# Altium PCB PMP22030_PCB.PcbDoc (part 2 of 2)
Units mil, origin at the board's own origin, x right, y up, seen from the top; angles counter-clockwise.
Board outline 4950 x 3450 mil, 4 copper layers (Top Layer, Signal Layer 1, Signal Layer 2, Bottom Layer), stack 55.6 mil thick; 125 components, 59 nets, 280 pads, 156 vias.
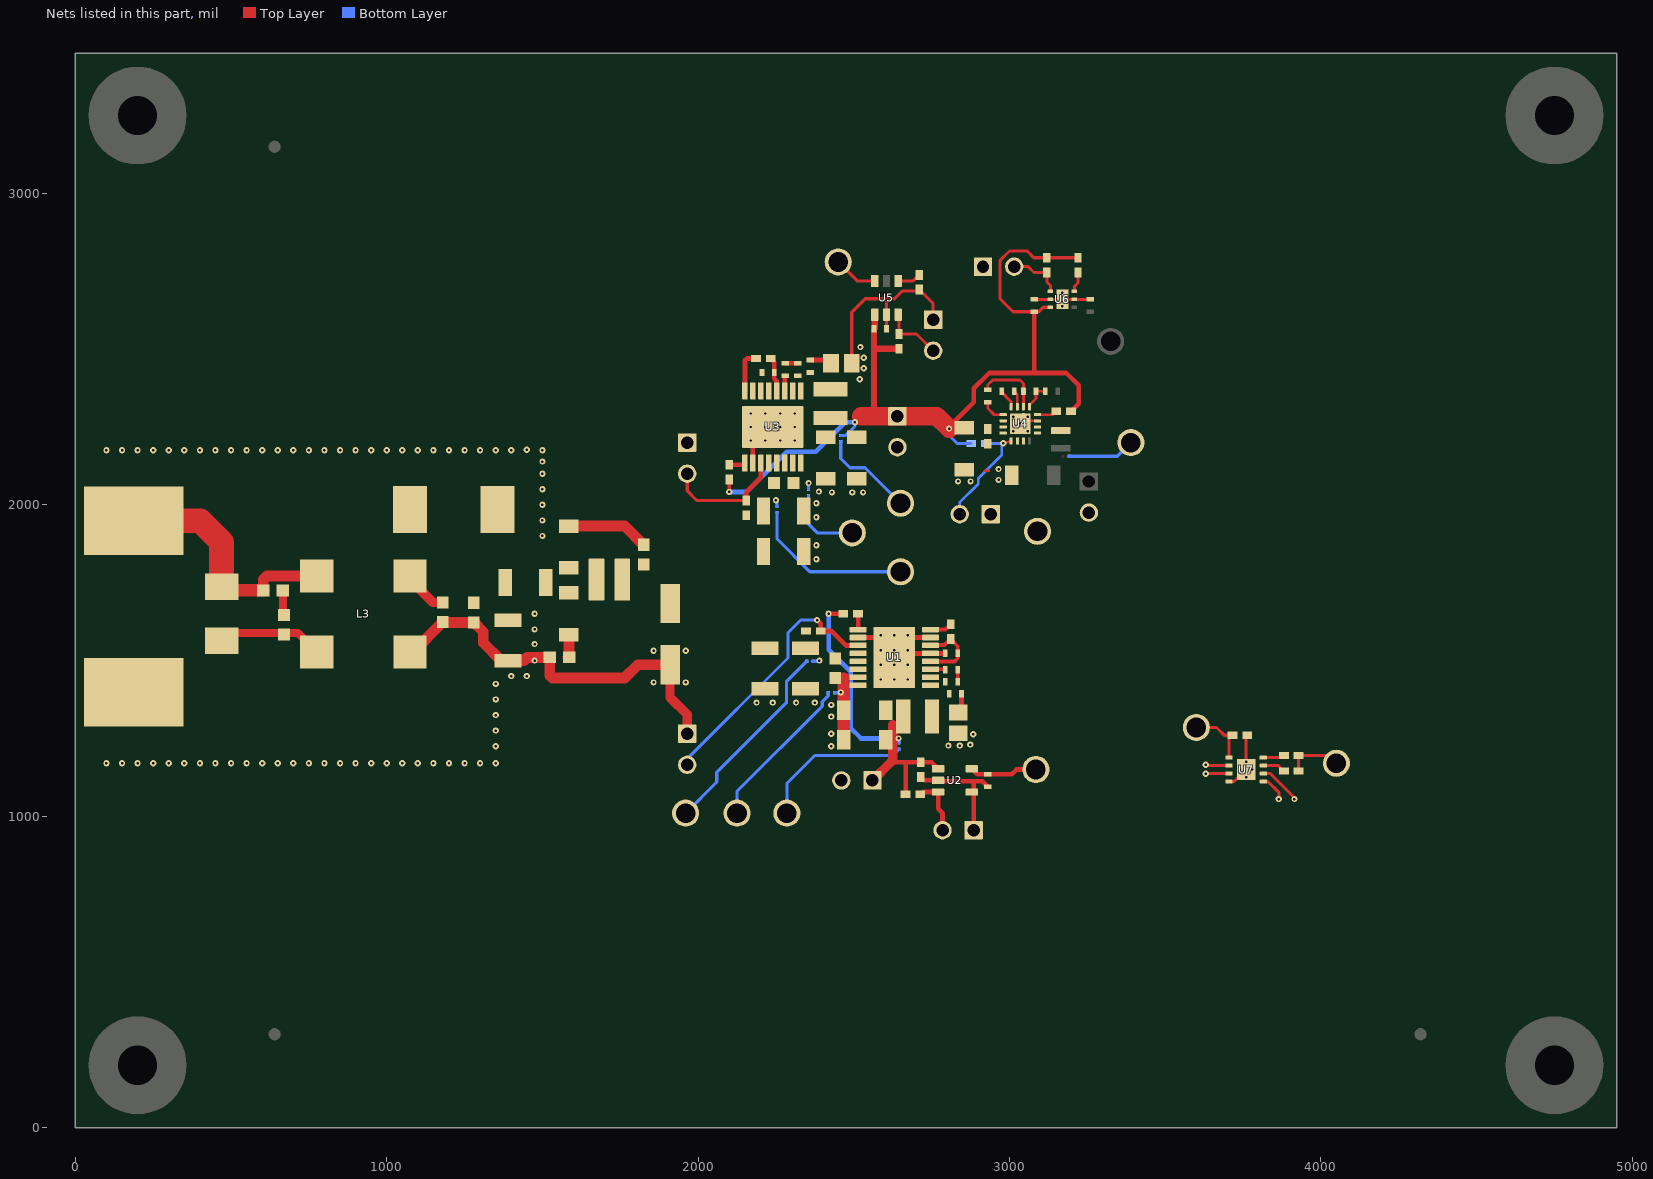
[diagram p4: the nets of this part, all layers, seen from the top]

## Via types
v1: diameter 20, hole 8, Top Layer to Bottom Layer, tented both sides, 121 vias
v2: diameter 19.68, hole 7.87, Top Layer to Bottom Layer, 23 vias
v3: diameter 19.68, hole 7.87, Top Layer to Bottom Layer, tented both sides, 12 vias

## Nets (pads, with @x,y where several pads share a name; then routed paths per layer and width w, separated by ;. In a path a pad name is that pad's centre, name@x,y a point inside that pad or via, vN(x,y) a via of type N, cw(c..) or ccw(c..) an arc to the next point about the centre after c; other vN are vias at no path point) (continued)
3V3: C25.1 C26.1 C27.1 C28.1 C33.1 C35.1 J7.1 L5.2 NT5.1 R12.1 R13.1 R16.2 R17.1 R18.1 R19.2 U4.10 U4.11 U4.12 U5.1 U6.6 | length 2907.1
  Top Layer w10: v1(2100,2041.46) R12.1@2100,2081.38 ; C33.1@2564.68,2564 C33.1@2567.6,2566.91 ; v1(2806.18,2245) 2853.07,2245 C27.1@2855,2246.93 ; U6.6@3131.61,2634.41 3108.91,2634.41 3094.5,2620 C35.1@3080,2620 3011.1,2620 2970,2661.1 2970,2785 3000,2815 3057,2815 3078.38,2793.62 R18.1@3120,2793.62 R19.2@3220,2793.62
  Top Layer w15: v1(2503.67,2265) 2523.67,2285 ; v1(2806.18,2245) 2806.18,2250.71 2885,2329.53 2885,2373.72 2934.73,2423.45 3080,2423.45 ; C35.1@3080,2620 3080,2423.45 ; R16.2@3197.68,2301 3222.06,2325.38 3222.06,2383.72 3182.34,2423.45 3080,2423.45
  Top Layer w20: C33.1@2564.68,2564 2564.68,2501.38 ; 2566.5,2285 2564.68,2286.81 2564.68,2501.38 ; C33.1@2567.6,2566.91 U5.1@2567.6,2610.87 ; J7.1@2640,2285 J7.1@2645,2290 ; R17.1@2645,2501.38 2564.68,2501.38
  Top Layer w60: 2523.67,2285 2566.5,2285 J7.1@2640,2285 2766.18,2285 v1(2806.18,2245)
  Bottom Layer w10: NT5.1@2458,2223 2474,2223 2503.67,2252.67 v1(2503.67,2265) ; v1(2806.18,2245) 2806.18,2222.82 2832,2197 R13.1@2877.06,2197
  Bottom Layer w15: v1(2100,2041.46) 2156.46,2041.46 2285,2170 2378.23,2170 2473.23,2265 v1(2503.67,2265)
3V3SW: 3V3SW.1 U5.6 | length 142.8
  Top Layer w10: 3V3SW.1@2450,2780 2510.87,2719.13 U5.6@2567.6,2719.13
5V: C15.1 C16.1 C17.1 J3.1 L4.2 NT2.1 R5.1 R6.1 U2.1 | length 1098.3
  Top Layer w15: v1(2419.21,1650) R5.1@2466.38,1650 ; 2625,1180 2618.62,1173.62 2670,1173.62 ; R6.1@2666.38,1070 2666.38,1170 2670,1173.62 ; U2.1@2770.87,1152.4 2749.65,1173.62 C17.1@2715,1173.62 2670,1173.62
  Top Layer w30: J3.1@2560,1115 2618.62,1173.62 ; 2625,1180 2625,1293.7
  Bottom Layer w10: NT2.1@2645,1235 v1@2645,1248.75
  Bottom Layer w15: v1(2419.21,1650) 2419.21,1534.26 2490,1463.47 2490,1282.9 2523.14,1249.76 v1(2643.99,1249.76) v1@2645,1248.75
AGND: C32.2 NT8.2 R15.1 U4.6 | length 216.3
  Top Layer w9: C32.2@2930,2370 2930,2385 2946.22,2401.22 3033.78,2401.22 3045,2390 R15.1@3045,2365 3044.84,2364.84 U4.6@3044.84,2315.12
CBOOT: R9.2 U3.3 | length 49.5
  Top Layer w15: U3.3@2278.39,2366.14 2278.39,2413.39 R9.2@2280,2415
CBOOT1: R3.2 U1.3 | length 48.2
  Top Layer w12: U1.3@2746.14,1471.61 2792.92,1471.61 R3.2@2793.89,1470.64
CGND: C7.1 D2.1 J2.1 L3.2 | length 341
  Top Layer w25: D2.1@470,1562.99 495.51,1588.5 670,1588.5 714.84,1588.5 L3.2@775.39,1527.95
CN: C31.2 U4.8 | length 62.5
  Top Layer w9: C31.2@2975,2365 2975,2361.61 3005.47,2331.14 U4.8@3005.47,2315.12
CP: C31.1 U4.7 | length 54.1
  Top Layer w9: C31.1@3015,2365 3025.13,2354.87 U4.7@3025.13,2315.15
CT: C36.2 U5.4 | length 75.7
  Top Layer w10: U5.4@2642.4,2719.13 2690.51,2719.13 C36.2@2710,2738.62
CWD: U7.2 | length 74.9
  Top Layer w10: v1@3630,1162.8 U7.2@3704.88,1162.8
  other v1: 3630,1165
EN: J8.2 R10.2 U3.11 | length 397.5
  Top Layer w10: J8.2@1965,2100 1965,2045 1996.38,2013.62 R10.2@2155,2013.62
  Top Layer w15: R10.2@2155,2013.62 2155,2040 2201.61,2086.61 U3.11@2201.61,2133.86
EN1: J4.2 R4.2 U1.11 | length 847.5
  Top Layer w15: v1(2382.07,1630) 2393.62,1618.44 R4.2@2393.62,1595 2427.99,1595 2474.61,1548.39 U1.11@2513.86,1548.39
  Bottom Layer w10: J4.2@1965,1165 1965,1184.18 2288.94,1508.12 2288.94,1588.88 2330.07,1630 v1(2382.07,1630)
EN1V1: J9.2 R13.2 U4.13 | length 367.1
  Top Layer w9: v1(2980,2197.99) U4.13@3005.47,2204.88
  Bottom Layer w9: J9.2@2840,1970 2840,2007.4 2899.6,2067 2899.6,2084.6 2975,2160 2975,2192.99 v1@2979.01,2197 ; R13.2@2924.31,2197 v1@2979.01,2197 ; v1(2980,2197.99) v1@2979.01,2197
EN1V8: J11.2 R18.2 U6.4 | length 178.3
  Top Layer w10: J11.2@3015,2765 3060,2765 3078.62,2746.38 R18.2@3120,2746.38 3120,2715.91 3131.61,2704.29 U6.4@3131.61,2685.59
ENL: J5.2 R6.2 U2.3 | length 188.8
  Top Layer w15: R6.2@2713.62,1070 2721.22,1077.6 U2.3@2770.87,1077.6 2770.87,1024.13 2785,1010 J5.2@2785,955
ENP: J10.2 R17.2 U5.3 | length 195.5
  Top Layer w10: U5.3@2642.4,2610.87 2645,2608.27 R17.2@2645,2548.62 2701.38,2548.62 J10.2@2755,2495
FB: R12.2 U3.9 | length 52.6
  Top Layer w15: R12.2@2100,2128.62 2145.2,2128.62 U3.9@2150.43,2133.86
FB1V1: R11.1 R15.2 U4.5 | length 88.4
  Top Layer w9: U4.5@3064.53,2315.12 3064.53,2320.66 3085,2341.13 R15.2@3085,2365 R11.1@3115,2365
FB_U1: R5.2 U1.9 | length 50.2
  Top Layer w15: U1.9@2513.86,1599.57 R5.2@2513.86,1649.76
GND: C2.2 C3.2 C5.2 C6.1 C8.2 C9.2 C12.2 C13.2 C14.2 C15.2 C16.2 C17.2 C18.2 C19.2 C22.2 C23.2 C24.2 C25.2 C26.2 C27.2 C28.2 C29.2 C30.2 C33.2 C34.2 C35.2 C36.1 C37.2 GND.1 J3.2 J4.1 J5.1 J6.2 J7.2 J8.1 J9.1 J10.1 J11.1 L3.3 NT3.2 NT7.2 NT8.1 R1.1 R2.1 R8.1 U1.5 U1.7 U1.10 U1.14 U1.15 U1.16 U1.17@2630,1510 U2.2 U2.4 U3.5 U3.6 U3.7 U3.10 U3.14 U3.15 U3.16 U3.17@2240,2250 U4.3 U4.14 U4.15 U4.17@3035,2260 U5.2 U6.2 U6.5 U6.7@3170,2660 U7.4 U7.9 | length 3800.3
  Top Layer w9: 2920.64,2109.53 2933.23,2109.53 ; v2(3035,2260) 3044.84,2269.84 U4.3@3090.12,2269.84
  Top Layer w10: R8.1@2493.46,2455 2493.46,2618.46 2536.69,2661.69 2605,2661.69 ; C33.2@2604.68,2564 2604.68,2610.55 U5.2@2605,2610.87 ; U5.2@2608.31,2614.17 U5.2@2605,2610.87 ; J10.1@2755,2595 2755,2646.38 C36.1@2710,2691.38 2705.2,2686.57 2655.47,2686.57 2630.59,2661.69 2605,2661.69 ; C35.2@3080,2660 U6.5@3131.61,2660 U6.7@3170,2660 U6.2@3208.39,2660 C34.2@3255,2660 ; U7.4@3704.88,1111.61 3721.61,1111.61 U7.9@3760,1150 3760,1256.38 C37.2@3763.62,1260 ; U5.2@2605,2610.87 2605,2661.69
  Top Layer w15: U3.10@2176.02,2133.86 2176.02,2186.02 U3.17@2240,2250 ; U1.10@2513.86,1573.98 2566.02,1573.98 U1.17@2630,1510 U1.17@2642.8,1522.8 ; C17.2@2715,1126.38 2726.38,1115 U2.2@2770.87,1115 2770.87,1112.13 2885,1112.13 ; U1.7@2746.14,1573.98 2693.98,1573.98 U1.17@2642.8,1522.8 ; C19.2@2793.99,1523.64 2793.15,1522.8 U1.5@2746.14,1522.8 U1.17@2642.8,1522.8 ; J5.1@2885,955 2885,1112.13 ; C18.2@2930,1095 2912.87,1112.13 2885,1112.13
  Top Layer w30: C2.2@1910,1486.57 1910,1381.56 1965,1326.56 J4.1@1965,1265
  Top Layer w35: L3.3@1074.61,1527.95 1084.45,1527.95 C6.1@1180,1623.5 1181,1622.5 C9.2@1280,1622.5 1310,1592.5 1310,1556.99 1366.95,1500.04 C8.2@1390,1500.04 1440.91,1500.04 1450.87,1510 R1.1@1523.5,1510 1523.5,1452.52 1532.52,1443.5 1763.65,1443.5 1806.72,1486.57 C2.2@1910,1486.57 ; C3.2@1585,1931.93 1764.57,1931.93 C5.2@1825,1871.5
  Top Layer w40: 2467.27,1441 2468.07,1440.2 C16.2@2468.07,1340 C15.2@2468.07,1245
  Bottom Layer w6: v1@2457,1396.64 v1(2458,1397.64)
  Bottom Layer w10: NT7.2@2355,2049.21 v1(2355,2070) ; NT3.2@2437.99,1396.64 v1@2457,1396.64
  other v1: 100,1170 150,1170 200,1170 250,1170 300,1170 350,1170 400,1170 450,1170 500,1170 550,1170 600,1170 650,1170 700,1170 750,1170 800,1170 850,1170 900,1170 950,1170 1000,1170 1050,1170 1100,1170 1150,1170 1200,1170 1250,1170 1300,1170 1350,1170 1350,1225 2427.99,1225 2804.03,1226.99 2840,1226.99 2874.37,1230.12 2884.03,1263.51 2427.99,1265 1350,1275 2427.99,1320 1350,1325 2427.99,1357.5 2187.67,1365 2240,1365 2314.8,1365 2375,1365 1350,1375 1350,1425 1856.97,1429.64 1960,1429.64 1400,1450 1450,1450 1475,1500 1856.97,1531.54 1960,1531.54 1475,1552.72 1475,1600 1475,1650 2380,1825 2380,1870 1500,1900 1500,1950 2380,1960 1500,2000 2380,2005 2430,2040 2495,2040 2530,2040 2388.1,2042.8 1500,2050 2835,2075 2875,2075 2965,2080 1500,2100 2965,2115 1500,2138.89 100,2175 150,2175 200,2175 250,2175 300,2175 350,2175 400,2175 450,2175 500,2175 550,2175 600,2175 650,2175 700,2175 750,2175 800,2175 850,2175 900,2175 950,2175 1000,2175 1050,2175 1100,2175 1150,2175 1200,2175 1250,2175 1300,2175 1350,2175 1400,2175 1500,2175 1450,2176.66 2519.46,2403.23 2532.3,2438.83 2532.3,2472.56 2521.32,2506.81
  other v2: 3760,1125.39 3740.31,1150 3779.69,1150 3760,1174.61 2586.69,1486.38 2630,1486.38 2673.31,1486.38 2586.69,1533.62 2630,1533.62 2673.31,1533.62 2216.38,2206.69 2263.62,2206.69 3011.77,2236.77 3058.23,2236.77 2216.38,2250 2263.62,2250 3011.77,2283.23 3058.23,2283.23 2216.38,2293.31 2263.62,2293.31 3170,2638.35 3170,2681.65
  other v3: 2586.69,1439.13 2630,1439.13 2673.31,1439.13 2586.69,1580.87 2630,1580.87 2673.31,1580.87 2169.13,2206.69 2310.87,2206.69 2169.13,2250 2310.87,2250 2169.13,2293.31 2310.87,2293.31
MR: U7.3 | length 75.1
  Top Layer w10: v1(3630,1136.65) 3630.55,1137.2 U7.3@3704.88,1137.2
Net1V1_1: 1V1.1 NT6.2 | length 216.5
  Bottom Layer w10: NT6.2@3191.68,2156 3346,2156 1V1.1@3390,2200
Net3V3_1: 3V3.1 NT5.2 | length 312
  Bottom Layer w10: 2458,2155 2458,2148.77 ; NT5.2@2458,2203 2458,2148.77 ; 3V3.1@2650,2005 2535.95,2119.05 2487.72,2119.05 2458,2148.77
Net3V3LDO_1: 3V3LDO.1 C18.1 U2.5 | length 219.3
  Top Layer w15: U2.5@2879.13,1152.4 2896.54,1135 C18.1@2930,1135 3007.76,1135 3022.76,1150 3V3LDO.1@3085,1150
Net5V_1: 5V.1 NT2.2 | length 500.6
  Bottom Layer w10: 5V.1@2285,1010 2285,1105 2375,1195 2625,1195 NT2.2@2645,1215
NetC1_1: C1.1 D2.2 J1.1 L3.1 | length 805.2
  Top Layer w25: D2.2@470,1737.01 D2.2@482.01,1725
  Top Layer w35: C1.1@603.5,1725 603.5,1760.55 615,1772.05 L3.1@775.39,1772.05
  Top Layer w40: D2.2@482.01,1725 C1.1@603.5,1725
  Top Layer w80: J1.1@187.01,1948.82 401.18,1948.82 470,1880 D2.2@470,1737.01
NetC1_2: C1.2 C7.2 | length 75
  Top Layer w25: C1.2@666.5,1725 666.5,1655 C7.2@670,1651.5
NetC4_2: C4.2 R1.2 | length 74.5
  Top Layer w35: R1.2@1581.5,1510 1585,1513.5 C4.2@1585,1583.07
NetC8_1: C8.1 C9.1 D1.1 L1.1
NetC10_1: C10.1 R2.2 | length 63.8
  Top Layer w15: R2.2@2835,1333.46 2846.18,1344.65 C10.1@2846.18,1392.64
NetC11_1: C11.1 R3.1 | length 39
  Top Layer w12: R3.1@2833.89,1470.64 2833.89,1431.74 C11.1@2833.99,1431.64
NetC20_1: C20.1 R8.2 | length 70.7
  Top Layer w15: C20.1@2360,2465 2416.54,2465 R8.2@2426.54,2455
NetC21_1: C21.1 R9.1 | length 40
  Top Layer w15: R9.1@2280,2455 C21.1@2320,2455
NetGNDS1_1: GNDS1.1 NT3.1 | length 508
  Bottom Layer w10: GNDS1.1@2125,1010 2125,1080 2398.7,1353.7 2398.7,1368.07 2417.99,1387.36 NT3.1@2417.99,1396.64
NetGNDS_1: GNDS.1 NT7.1 | length 243.1
  Bottom Layer w10: NT7.1@2355,2029.21 2355,1960 2355,1937.47 2382.47,1910 2405,1910 GNDS.1@2495,1910
NetNT1_2: NT1.2 VIN2.1 | length 648.8
  Bottom Layer w10: VIN2.1@1960,1010 2060,1110 2060,1140.87 2283.38,1364.25 2283.38,1431.93 NT1.2@2349.09,1497.64
NetNT4_2: NT4.2 VIN1.1 | length 524.8
  Bottom Layer w10: NT4.2@2253.35,1975 2253.35,1890.63 2358.98,1785 VIN1.1@2650,1785
NetR20_2: R20.2 R21.2 TP13.1 | length 181.7
  Top Layer w10: R21.2@3928.62,1145 R20.2@3928.62,1195 4025,1195 TP13.1@4050,1170
PG1V1: R16.1 U4.4 | length 65.1
  Top Layer w9: U4.4@3090.12,2289.53 3138.97,2289.53 R16.1@3150.44,2301
PG1V8: R19.1 U6.3 | length 65.6
  Top Layer w10: U6.3@3208.39,2685.59 3208.39,2700.81 3220,2712.43 R19.1@3220,2746.38
PGOOD: R14.2 U3.8 | length 136.3
  Top Layer w15: U3.8@2150.43,2366.14 2150.43,2463.98 2156.46,2470 R14.2@2186.38,2470
PGOOD1: R7.2 U1.8 | length 71.8
  Top Layer w12: U1.8@2746.14,1599.57 2794.3,1599.57 R7.2@2810.99,1616.26
RSET: R20.1 U7.8 | length 69
  Top Layer w10: U7.8@3815.12,1188.39 3874.76,1188.39 R20.1@3881.38,1195
SET1: U7.5 | length 86
  Top Layer w10: U7.5@3815.12,1111.61 3829.95,1111.61 3865,1076.56 v1(3865,1055)
SS1V1: C32.1 U4.9 | length 78.1
  Top Layer w9: C32.1@2930,2330 2930,2310.5 2950.97,2289.53 U4.9@2979.88,2289.53
SW: C20.2 C21.2 L5.1 U3.1 U3.2
SW1: C10.2 C11.2 L4.1 U1.1 U1.2
SW1V1: L6.1 U4.1 U4.2
VBATT: C6.2 D1.2 L3.4 | length 147.7
  Top Layer w30: L3.4@1074.61,1772.05 1074.61,1760.39 1148.5,1686.5 C6.2@1180,1686.5
VCC: C30.1 R14.1 U3.4 | length 111.8
  Top Layer w15: R14.1@2233.62,2470 2245,2458.62 C30.1@2245,2425 2245,2405.36 2252.8,2397.57 U3.4@2252.8,2366.14
VCC1: C19.1 R7.1 U1.4 U1.6 | length 237.2
  Top Layer w12: U1.4@2746.14,1497.2 2823.7,1497.2 2833.99,1507.5 C19.1@2833.99,1523.64 2833.99,1546.02 R7.1@2810.99,1569.02 2791.49,1549.51 2746.14,1549.51 U1.6@2746.14,1548.39
VDD: C37.1 TP12.1 U7.1 | length 203.1
  Top Layer w10: TP12.1@3600,1285 3665,1285 3690,1260 C37.1@3716.38,1260 3704.88,1248.5 U7.1@3704.88,1188.39
VFILT: C3.1 C4.1 L1.2 L2.1
VIN: C2.1 C5.1 C12.1 C13.1 C14.1 C22.1 C23.1 C24.1 L2.2 NT1.1 NT4.1 R4.1 R10.1 U1.12 U1.13 U3.12 U3.13 | length 42.8
  Bottom Layer w10: v1(2250,2015) 2253.35,2011.65 NT4.1@2253.35,1995 ; NT1.1@2369.09,1497.64 2387.2,1497.64 v1(2389.57,1500)
WDI: U7.6 | length 136.9
  Top Layer w10: U7.6@3815.12,1137.2 3837.8,1137.2 3915,1060 v1(3915,1055)
WDO: R21.1 U7.7 | length 73.6
  Top Layer w10: U7.7@3815.12,1162.8 3863.58,1162.8 R21.1@3881.38,1145
pads on no net: FID1.1 FID2.1 FID3.1 H1.1 H2.1 H3.1 H4.1 H5.0 H6.0 H7.0 H8.0 LBL1.0 U1.17@2630,1510 U3.17@2240,2250 U4.17@3035,2260 U5.5 U6.7@3170,2642.28 U6.7@3170,2677.72

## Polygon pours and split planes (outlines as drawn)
GND on Signal Layer 1 "SIGNAL_LAYER_1_GND_P004" (solid, remove dead copper, pour order 4): 0,0 0,3450 4950,3450 4950,0
GND on Top Layer "TOP_LAYER_GND_P000" (solid, remove dead copper, pour order 0): 0,0 0,3450 4950,3450 4950,0
GND on Signal Layer 2 "SIGNAL_LAYER_2_GND_P006" (solid, remove dead copper, pour order 6): 0,0 0,3450 4950,3450 4950,0
GND on Bottom Layer "BOTTOM_LAYER_GND_P008" (solid, remove dead copper, pour order 8): 0,0 0,3450 4950,3450 4950,0

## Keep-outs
Keep-Out Layer:
  text ".Layer_Name" at 577,-858.49 h60

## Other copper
Top Layer:
  region net VIN: 1866.73,1616.26 2043.86,1616.26 2043.86,1492.64 2259.21,1492.64 2259.21,1982.13 1866.73,1982.13
  pour cut-out: 0,1195 1295,1195 1295,2150 5,2150
  region net GND: 3000,2144.57 2804.61,2144.57 2804.61,2050 3000,2050
  region net GND: 3020,2237.5 3020,2175.35 2985,2140.35 2985,2050 3050,2050 3050,2237.5
  region net 1V1: 3115,2198.7 3115,2061.3 3205,2061.3 3205,2198.7
  region net SW1V1: 3080,2255 3200.43,2255 3200.43,2220 3080,2220
  region net 3V3: 2990,2269.83 2823.7,2270 2823.7,2225 2990,2225
  region net GND: 2170,2310 2233.62,2310 2233.62,2391.93 2225,2400.55 2225,2440 2170,2440
  region net 3V3: 2367.5,2305 2367.5,2195 2549.37,2195 2549.37,2305
  region net SW: 2300,2341.13 2300,2401.22 2306.22,2407.44 2306.22,2430 2375,2430 2388.1,2416.9 2464.95,2416.9 2481.85,2400 2481.85,2340
  region net VIN: 2260,2161.5 2260,1798.07 2135,1798.07 2135,1982.13 2172.17,1982.13 2222.87,2032.84 2222.87,2161.5
  region net GND: 2274.06,2163.39 2274.06,2049.21 2315,2049.21 2315,1805.12 2420,1805.12 2420,2009.97 2555,2010.07 2555,2163.39
  region net VIN: 2170,1518.46 2170,1608.43 2365,1608.43 2365,1518.46
  region net GND: 2169.13,1471.61 2481.85,1471.61 2481.85,1480 2595,1480 2595,1390 2169.13,1390
  region net VIN: 2543.39,1530 2543.39,1490 2170,1490 2170,1530
  region net 5V: 2683.33,1377.4 2575,1377.4 2575,1210 2683.33,1210
  region net SW1: 2720,1265 2720,1450 2778.79,1450 2783.37,1445.42 2817.18,1445.42 2817.18,1378.86 2804.61,1378.86 2780,1354.25 2780,1265
  region net VIN: 1730,1829.57 1945,1829.57 1945,1615 1730,1615
  region net VFILT: 1700,1829.57 1477.89,1829.57 1477.89,1690 1700,1690
  region net NetC8_1: 1260,1665 1260,2061.01 1435,2061.01 1435,1605 1345,1605 1345,1665
  region net VBATT: 1020,2060 1021.01,2061.01 1135,2061.01 1135,1713.98 1020,1713.98
  region net CGND: 850,1605 850,1277.64 847.64,1280 35,1280 35,1605
  text ".Layer_Name" at 577,-858.49 h60
Signal Layer 1:
  pour cut-out: 0,1195 1295,1195 1295,2150 5,2150
Signal Layer 2:
  pour cut-out: 0,1195 1295,1195 1295,2150 5,2150
Bottom Layer:
  pour cut-out: 0,1195 1295,1195 1295,2150 5,2150
  region: 2120.5,2438.78
  text ".Layer_Name" at 577,-858.49 h60

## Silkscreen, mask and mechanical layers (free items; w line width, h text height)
Top Overlay:
  text "EN 1V8" at 3043.35,2835 h72.83 r90
  text "GND" at 2937,2831 h72.83 r90
  text "GND" at 2820,2565 h72.83
  text "EN 3V3SW" at 2817.6,2505 h72.83
  text "3V3" at 2615,2237.5 h72.83
  text "GND" at 1755,2182 h72.83
  text "GND" at 2750,2100 h72.83 r90
  text "EN 3V3" at 1680,2073 h72.83
  text "1V1" at 3310,2052 h72.83
  text "GND" at 3181.68,1911 h72.83
  text "EN 1V1" at 2860,1695 h72.83 r90
  text "GND" at 2995,1625 h72.83 r90
  text "GND" at 1739,1239 h72.83
  text "EN 5V" at 1706,1137 h72.83
  text "GND" at 2485,910 h72.83 r90
  text "WATCHDOG / SUPERVISOR" at 3599.86,884 h72.83
  text "5V" at 2590,880 h72.83 r90
  text "GND" at 2908.85,710 h72.83 r90
  text "EN 3V3LDO" at 2817.18,645 h72.83 r90
  text "'.PRJ_Number'.PCB_Rev" at 1845,125.77 h108.27
  text ".Layer_Name" at 577,-858.49 h60
Bottom Overlay:
  text ".Layer_Name" at 577,-858.49 h60
Top Paste:
  text ".Layer_Name" at 577,-858.49 h60
Bottom Paste:
  text ".Layer_Name" at 577,-858.49 h60
Top Solder:
  text ".Layer_Name" at 577,-858.49 h60
  text ".Layer_Name" at 577,-858.49 h60
Bottom Solder:
  text ".Layer_Name" at 577,-858.49 h60
Drill Guide:
  text ".Layer_Name" at 577,-858.49 h60
M1 Board Outline:
  the board outline again, w10
  text ".Layer_Name" at 577,-858.49 h60
M2 Board Dimensions:
  rectangle: 0,-275 125,-150
  rectangle: 125,-400 500,-275
  lines w7: 0,-275 1000,-275 ; 125,-400 125,-150 ; 250,-400 250,-150 ; 500,-400 500,-150 ; 750,-400 750,-150 ; 0,-400 1000,-400 1000,-150 0,-150 0,-400
  text ".Layer_Name" at 577,-858.49 h60
M3 3D STEP Top:
  text ".Layer_Name" at 577,-858.49 h60
M4 3D STEP Bottom:
  text ".Layer_Name" at 577,-858.49 h60
M5 Assembly Top:
  lines w10: -292,-930.17 6308,-930.17 ; -292,-726.83 6310,-726.83 ; -292,-523.5 -292,-1133.5 3713,-1133.5 6310,-1133.5 6310,-523.5 -291.5,-523.5 -291.5,-1133.5 1284,-1133.5 ; 2173,-1133.5 2173,-523.5 ; 3440,-726.83 3440,-523.5 ; 4280,-726.83 4280,-523.5 ; 4902,-1140 4902,-937.17
  text "COMPONENTS MARKED 'DNP' SHOULD NOT BE POPULATED." at 1153.5,-318.5 h60
  text "ASSEMBLY VARIANT:" at 1153,-434 h60
  text ".VariantName" at 2189,-434 h60
  text "PCB VIEWED FROM TOP SIDE" at -228.5,-655.67 h60
  text "BOARD #:" at 2248,-655.67 h60
  text ".PRJ_Number" at 2793.5,-655.67 h60
  text "REV:" at 3638,-655.67 h60
  text ".PCB_Rev" at 3929.5,-655.67 h60
  text "SVN REV:" at 4476,-655.67 h60
  text ".VersionControl_RevNumber" at 4982,-655.67 h60
  text "TID #:" at 2248,-859 h60
  text ".TID" at 2793.5,-859 h60
  text "PLOT NAME =" at -228.5,-1064.34 h60
  text ".plot_File_Name" at 577,-1064.34 h60
  text "GENERATED    :" at 2250,-1064.34 h60
  text ".Print_Date" at 3119.5,-1064.34 h60
  text ".Print_Time" at 3848.5,-1064.34 h60
  text "TEXAS INSTRUMENTS" at 5113,-1064.34 h60
M6 Assembly Bottom:
  lines w10: -292.5,-727.33 6309.5,-727.33 ; -290.5,-930.67 6309.5,-930.67 ; 1115.5,-1140.5 1115.5,-937.67 ; 1737.5,-727.33 1737.5,-524 ; 2577.5,-727.33 2577.5,-524 ; 3844.5,-1134 3844.5,-524 ; 4733.5,-1134 6309,-1134 6309,-524 -292.5,-524 -292.5,-1134 2304.5,-1134 6309.5,-1134 6309.5,-524
  text "COMPONENTS MARKED 'DNP' SHOULD NOT BE POPULATED." at 6102,-318 h60
  text ".VariantName" at 5058,-434 h60
  text "ASSEMBLY VARIANT:" at 6097,-434 h60
  text ".VersionControl_RevNumber" at 1035.5,-656.17 h60
  text "SVN REV:" at 1541.5,-656.17 h60
  text ".PCB_Rev" at 2088,-656.17 h60
  text "REV:" at 2379.5,-656.17 h60
  text ".PRJ_Number" at 3224,-656.17 h60
  text "BOARD #:" at 3769.5,-656.17 h60
  text "PCB VIEWED FROM BOTTOM SIDE" at 6246,-656.17 h60
  text ".TID" at 3224,-859.5 h60
  text "TID #:" at 3769.5,-859.5 h60
  text "TEXAS INSTRUMENTS" at 904.5,-1064.84 h60
  text ".Print_Time" at 2169,-1064.84 h60
  text ".Print_Date" at 2898,-1064.84 h60
  text "GENERATED    :" at 3767.5,-1064.84 h60
  text ".plot_File_Name" at 5440.5,-1064.84 h60
  text "PLOT NAME =" at 6246,-1064.84 h60
M9 Title Sheet:
  drawing of 57 lines, arcs and shapes, not listed
  text "1" at 739.84,8036.5 h70
  text "2" at 3235.5,8036.5 h70
  text "3" at 5724.84,8036.5 h70
  text "4" at 8231.51,8036.5 h70
  text "5" at 10730.5,8036.5 h70
  text "6" at 13235.5,8036.5 h70
  text "A" at -416.5,6893.5 h70
  text "A" at 14383.5,6893.5 h70
  text "B" at -416.5,4513.5 h70
  text "B" at 14383.5,4513.5 h70
  text "C" at -416.5,2138.5 h70
  text "C" at 14383.5,2138.5 h70
  text "PROJECT TITLE:" at 11343.5,277.5 h45
  text ".PRJ_Title" at 11393.5,144.17 h70
  text "DESIGNED FOR:" at 11343.5,-23.5 h45
  text ".PRJ_Customer" at 11393.5,-163.5 h70
  text "D" at -416.5,-231.5 h70
  text "D" at 14383.5,-231.5 h70
  text "FILE NAME:" at 11343.5,-323.5 h45
  text ".PCB_File_Name_No_Path" at 11393.5,-443.5 h70
  text "Texas Instruments (TI) and/or its licensors do not warrant the accuracy or completeness of this specification" at 6374,-605.34 h45
  text "ENGINEER:" at 11343.5,-613.5 h45
  text "LAYOUT BY:" at 12848.5,-613.5 h45
  text "or any information contained therein. TI and/or its licensors do not warrant that this design will meet" at 6329.01,-718 h45
  text ".PRJ_Engineer" at 11393.5,-768.49 h70
  text ".PCB_Layout" at 12899,-768.49 h70
  text "the specifications, will be suitable for your application or fit for any particular purpose, or will operate in" at 6329.01,-830.67 h45
  text ".Layer_Name" at 577,-858.49 h60
  text "ALTIUM DESIGNER VERSION:" at 12848.5,-923.5 h45
  text "an implementation. TI and/or its licensors do not warrant that the design is production worthy. You should" at 6329.01,-943.33 h45
  text "completely validate and test your design implementation to confirm the system functionality for your application." at 6374,-1056 h45
  text ".print_Scale" at 11393.5,-1056.83 h70
  text ".Application_BuildNumber" at 12899,-1056.83 h70
  text "1" at 739.84,-1263.5 h70
  text "2" at 3235.5,-1263.5 h70
  text "3" at 5724.84,-1263.5 h70
  text "4" at 8231.51,-1263.5 h70
  text "5" at 10730.5,-1263.5 h70
  text "6" at 13235.5,-1263.5 h70
M10 Fab Notes:
  drawing of 189 lines, arcs and shapes, not listed
  text "DESIGN INFORMATION" at 12382.02,6356.17 h60
  text "MIN. TRACK WIDTH:" at 11737.46,6224.05 h60
  text "8" at 12833.7,6224.05 h60
  text "MIL" at 12988.46,6224.05 h60
  text "MIN. CLEARANCE:" at 11737.46,6099.92 h60
  text "0.2" at 12773.7,6099.93 h60
  text "mm" at 12988.46,6099.92 h60
  text "MIN. VIA PAD SIZE:" at 11737.46,5975.8 h60
  text "24" at 12803.71,5975.8 h60
  text "MIL" at 12988.46,5975.8 h60
  text "0.05mm (2MIL)" at 12432.46,5845.9 h60
  text "MINIMUM ANNULAR RING" at 11408.23,5837.67 h60
  text "EXTERNAL" at 13140.46,5837.67 h60
  text "PER" at 11608.23,5727.55 h60
  text "IPC-D-275 CLASS 2 LEVEL C" at 11828.23,5727.54 h60
  text "MIL, HOLES" at 13316.46,5627.07 h60
  text "+/-" at 12924,5618.48 h60
  text "+/-" at 13778,5618.48 h60
  text "REGISTRATION TOLERANCES:" at 11408.23,5617.42 h60
  text "METAL" at 12608,5617.42 h60
  text "5" at 13184.2,5617.42 h60
  text "3" at 14017.2,5617.42 h60
  text "MIL" at 14133.46,5617.42 h60
  text "HOLE SIZE TOLERANCE (UNLESS OTHERWISE SPECIFIED):" at 11408.23,5519.1 h60
  text "+/-" at 13778,5516.23 h60
  text "3" at 14017.2,5515.17 h60
  text "MIL" at 14133.46,5515.17 h60
  text "MATERIAL:" at 11333.46,5377.52 h60
  text "FR-4 High Tg" at 12319.9,5249 h60
  text "X" at 12175.46,5241.01 h60
  text "FR-408" at 11754.46,5236.49 h60
  text "OTHER" at 13242.46,5236.49 h60
  text "62 MIL (1.6mm) +/-10%" at 12074.56,5093.46 h60
  text "X" at 11954.46,5091.01 h60
  text "THICKNESS:" at 11408.23,5085.24 h60
  text "OTHER" at 13359.46,5085.24 h60
  text "TOLERANCE:" at 11408.23,4946.92 h60
  text "X" at 12256.46,4946.92 h60
  text "ANSI IPC-6012 TYPE 3 CLASS 2" at 12434.48,4946.92 h60
  text "OTHER +/-" at 12434.46,4802.73 h60
  text "BOW & TWIST:" at 11408.23,4657.54 h60
  text "X" at 12256.46,4657.54 h60
  text "ANSI IPC-6012 TYPE 3 CLASS 2" at 12434.48,4657.54 h60
  text "OTHER +/-" at 12434.46,4510.85 h60
  text "DRILLING:" at 11333.46,4380.23 h60
  text "NC_DRILL FILES" at 13094.46,4275.04 h60
  text "REFERENCE:" at 11408.23,4271.1 h60
  text "X" at 12065.46,4271.01 h60
  text "AS SHOWN" at 12243.46,4271.1 h60
  text "X" at 12966.46,4271.1 h60
  text "OTHER" at 13392.46,4128.85 h60
  text "PTH COPPER THICKNESS:" at 11407.91,4125.32 h60
  text "X" at 12547.14,4125.32 h60
  text "20-30 um" at 12675.14,4125.32 h60
  text "BOARD FINISH:" at 11333.46,3977.73 h60
  text "SILKSCREEN:" at 11488.68,3867.6 h60
  text "X" at 12446.46,3867.6 h60
  text "TOP" at 12563.46,3867.6 h60
  text "X" at 12956.46,3867.6 h60
  text "BOTTOM" at 13074.46,3867.6 h60
  text "SILKSCREEN COLOR:" at 11488.68,3712.41 h60
  text "X" at 12445.46,3712.41 h60
  text "WHITE" at 12563.46,3712.41 h60
  text "OTHER" at 13074.46,3712.41 h60
  text "X" at 12576.46,3568.96 h60
  text "GREEN" at 12694.46,3568.96 h60
  text "OTHER" at 13312.46,3568.96 h60
  text "SOLDER RESIST COLOR:" at 11488.68,3562.1 h60
  text "X" at 12576.46,3414.71 h60
  text "MATTE" at 12694.46,3414.71 h60
  text "SEMI-GLOSS" at 13312,3414.07 h60
  text "IMMERSION GOLD (ENIG)" at 12394.46,3241.94 h60
  text "ENEPIG" at 13732,3234.72 h60
  text "SURFACE FINISH:" at 11333.46,3233.72 h60
  text "X" at 12216.46,3233.72 h60
  text "IMM. TIN/SILVER OR EQUIV" at 11663,3096.4 h60
  text "OTHER" at 13094.46,3092.47 h60
  text "ARRAY/PANEL:" at 11333.46,2937.09 h60
  text "CUT AND TRIM PER M1 BOARD OUTLINE" at 12394.46,2928.87 h60
  text "N.C. ROUTE" at 12394.46,2792.9 h60
  text "X" at 13082.46,2792.9 h60
  text "V. SCORE" at 13260.46,2792.9 h60
  text "CERTIFICATION:" at 11333.46,2663.77 h60
  text "MATERIALS AND WORKMANSHIP FOR ALL PCBS" at 12058.46,2663.77 h60
  text "TO MEET OR EXCEED THE REQUIREMENTS OF:" at 12058.46,2569.71 h60
  text "X" at 11695.97,2441.08 h60
  text "ANSI IPC-A-600F CLASS ->" at 11823.96,2441.08 h60
  text "X" at 13471.97,2441.08 h60
  text "2" at 13581.96,2441.08 h60
  text "1" at 13266.96,2439.58 h60
  text "3" at 13935.96,2439.58 h60
  text "X" at 12507.97,2293.39 h60
  text "RoHS" at 12635.96,2293.39 h60
  text "OTHER" at 13280.36,2293.39 h60
  text "PER ORDER" at 13677.42,2293.39 h60
  text "ALL BOARDS MUST MEET OR EXCEED UL94-V0 REQUIREMENTS." at 11361,2139.57 h60
  text "PCB MUST BEAR THE UL94V-0 UL REGISTERED MATERIAL ID NUMBER" at 11361,2023.5 h60
  text "ADDITIONAL REQUIREMENTS:" at 11333.46,1854.08 h60
  text "MICROSECTION:" at 11408.23,1746.95 h60
  text "YES" at 12313.96,1746.95 h60
  text "REQUIRED" at 13175.46,1602.62 h60
  text "BARE BOARD ELEC. TEST:" at 11408.23,1599.76 h60
  text "NONE" at 12713.96,1599.76 h60
  text "X" at 13057.46,1599.76 h60
  text "PER ORDER" at 13767.46,1599.76 h60
  text "XX MIL VIAS REQUIRE NON-CONDUCTIVE FILL AND PLANARIZE" at 11576.38,1394.82 h59
  text "XX MIL VIAS REQUIRE CONDUCTIVE FILL AND PLANARIZE" at 11584.38,1290.84 h60
  text "OUTER XX MIL TRACES REQUIRE 50 OHM SINGLE-ENDED IMPEDANCE" at 11583.39,1127.46 h58
  text "LAYER 2 & 3 (INNER LAYERS) XX MIL WIDE, XX MIL SPACE / TRACES REQUIRE 100 OHM DIFFERENTIAL IMPEDANCE" at 11575.39,891.74 h60
  text ".Layer_Name" at 577,-858.49 h60
M11 Gerber Information:
  lines w10: -292,-930.17 6308,-930.17 ; -292,-726.83 6310,-726.83 ; -292,-523.5 -292,-1133.5 3713,-1133.5 6310,-1133.5 6310,-523.5 -291.5,-523.5 -291.5,-1133.5 1284,-1133.5 ; 2173,-1133.5 2173,-523.5 ; 3440,-726.83 3440,-523.5 ; 4280,-726.83 4280,-523.5 ; 4902,-1140 4902,-937.17
  text "ALL ARTWORK VIEWED FROM TOP SIDE" at -228.5,-655.67 h60
  text "BOARD #:" at 2248,-655.67 h60
  text ".PRJ_Number" at 2793.5,-655.67 h60
  text "REV:" at 3638,-655.67 h60
  text ".PCB_Rev" at 3929.5,-655.67 h60
  text "SVN REV:" at 4476,-655.67 h60
  text ".VersionControl_RevNumber" at 4982,-655.67 h60
  text "LAYER NAME =" at -228.5,-858.49 h60
  text "TID #:" at 2248,-859 h60
  text ".TID" at 2793.5,-859 h60
  text "PLOT NAME =" at -228.5,-1064.34 h60
  text ".plot_File_Name" at 577,-1064.34 h60
  text "GENERATED    :" at 2250,-1064.34 h60
  text ".Print_Date" at 3119.5,-1064.34 h60
  text ".Print_Time" at 3848.5,-1064.34 h60
  text "TEXAS INSTRUMENTS" at 5113,-1064.34 h60
M12 Stackup:
  drawing of 295 lines, arcs and shapes, not listed
  text "Layer" at 5822.5,7392.5 h60
  text "Name" at 6232.41,7392.5 h60
  text "Material" at 7172.15,7392.5 h60
  text "Thickness" at 8031.92,7392.5 h60
  text "Constant" at 8681.76,7392.5 h60
  text "Board Layer Stack" at 9251.62,7392.5 h60
  text "1" at 5822.5,7272.5 h60
  text "Top Overlay" at 6232.41,7272.5 h60
  text "2" at 5822.5,7152.5 h60
  text "Top Solder" at 6232.41,7152.5 h60
  text "Solder Resist" at 7172.15,7152.5 h60
  text "0.40mil" at 8031.92,7152.5 h60
  text "3.5" at 8681.76,7152.5 h60
  text "3" at 5822.5,7032.5 h60
  text "Top Layer" at 6232.41,7032.5 h60
  text "Copper" at 7172.15,7032.5 h60
  text "1.40mil" at 8031.92,7032.5 h60
  text "4" at 5822.5,6912.5 h60
  text "Dielectric 2" at 6232.41,6912.5 h60
  text "5.00mil" at 8031.92,6912.5 h60
  text "4.2" at 8681.76,6912.5 h60
  text "5" at 5822.5,6792.5 h60
  text "Signal Layer 1" at 6232.41,6792.5 h60
  text "Copper" at 7172.15,6792.5 h60
  text "1.40mil" at 8031.92,6792.5 h60
  text "6" at 5822.5,6672.5 h60
  text "Dielectric1" at 6232.41,6672.5 h60
  text "FR-4" at 7172.15,6672.5 h60
  text "40.00mil" at 8031.92,6672.5 h60
  text "4.8" at 8681.76,6672.5 h60
  text "7" at 5822.5,6552.5 h60
  text "Signal Layer 2" at 6232.41,6552.5 h60
  text "Copper" at 7172.15,6552.5 h60
  text "1.40mil" at 8031.92,6552.5 h60
  text "8" at 5822.5,6432.5 h60
  text "Dielectric 3" at 6232.41,6432.5 h60
  text "5.00mil" at 8031.92,6432.5 h60
  text "4.2" at 8681.76,6432.5 h60
  text "9" at 5822.5,6312.5 h60
  text "Bottom Layer" at 6232.41,6312.5 h60
  text "Copper" at 7172.15,6312.5 h60
  text "1.40mil" at 8031.92,6312.5 h60
  text "10" at 5822.5,6192.5 h60
  text "Bottom Solder" at 6232.41,6192.5 h60
  text "Solder Resist" at 7172.15,6192.5 h60
  text "0.40mil" at 8031.92,6192.5 h60
  text "3.5" at 8681.76,6192.5 h60
  text "11" at 5822.5,6072.5 h60
  text "Bottom Overlay" at 6232.41,6072.5 h60
  text ".Layer_Name" at 577,-858.49 h60
M13 Component Bodies Top:
  text ".Layer_Name" at 577,-858.49 h60
M14 Component Bodies Bottom:
  text ".Layer_Name" at 577,-858.49 h60
M15 Courtyards Top:
  text ".Layer_Name" at 577,-858.49 h60
M16 Courtyards Bottom:
  text ".Layer_Name" at 577,-858.49 h60
Drill Drawing:
  circle w10: c5123.72,2581.49 r27.63
  lines w10: 5096.09,2678.19 5151.34,2678.19 5151.34,2733.44 5096.09,2733.44 5096.09,2678.19 ; 5096.09,2857.76 5151.34,2857.76 5123.72,2802.51 5096.09,2857.76 ; 5096.09,2926.83 5123.72,2940.64 5151.34,2926.83 5137.53,2954.45 5151.34,2982.08 5123.72,2968.27 5096.09,2982.08 5109.9,2954.45 5096.09,2926.83 ; 5096.09,3064.96 5109.9,3064.96 5123.72,3051.15 5137.53,3064.96 5151.34,3064.96 5137.53,3078.77 5151.34,3092.59 5137.53,3092.59 5123.72,3106.4 5109.9,3092.59 5096.09,3092.59 5109.9,3078.77 5096.09,3064.96
  lines w12: 5046,2516.57 8277.49,2516.57 ; 5046,3138.17 8277.49,3138.17 ; 5383.86,2392.25 5383.86,3262.49 ; 5715.86,2392.25 5715.86,3262.49 ; 6352.43,2392.25 6352.43,3262.49 ; 6611.57,2392.25 6611.57,3262.49 ; 6986.72,2392.25 6986.72,3262.49 ; 7711.05,2392.25 7711.05,3262.49 ; 5046,2392.25 8277.49,2392.25 8277.49,3262.49 5046,3262.49 5046,2392.25
  text "Symbol" at 5120.59,3175.47 h72
  text "Quantity" at 5421.16,3175.47 h72
  text "Finished Hole Size" at 5753.16,3175.47 h72
  text "Plated" at 6389.72,3175.47 h72
  text "Hole Type" at 6648.86,3175.47 h72
  text "Drill Layer Pair" at 7024.02,3175.47 h72
  text "Hole Tolerance" at 7748.35,3175.47 h72
  text "35" at 5421.16,3051.15 h60
  text "7.87mil (0.200mm)" at 5753.16,3051.15 h60
  text "PTH" at 6389.72,3051.15 h60
  text "Round" at 6648.86,3051.15 h60
  text "Top Layer - Bottom Layer" at 7024.02,3051.15 h60
  text "121" at 5421.16,2926.83 h60
  text "8.00mil (0.203mm)" at 5753.16,2926.83 h60
  text "PTH" at 6389.72,2926.83 h60
  text "Round" at 6648.86,2926.83 h60
  text "Top Layer - Bottom Layer" at 7024.02,2926.83 h60
  text "18" at 5421.16,2802.51 h60
  text "40.00mil (1.016mm)" at 5753.16,2802.51 h60
  text "PTH" at 6389.72,2802.51 h60
  text "Round" at 6648.86,2802.51 h60
  text "Top Layer - Bottom Layer" at 7024.02,2802.51 h60
  text "13" at 5421.16,2678.19 h60
  text "63.00mil (1.600mm)" at 5753.16,2678.19 h60
  text "PTH" at 6389.72,2678.19 h60
  text "Round" at 6648.86,2678.19 h60
  text "Top Layer - Bottom Layer" at 7024.02,2678.19 h60
  text "4" at 5421.16,2553.87 h60
  text "125.98mil (3.200mm)" at 5753.16,2553.87 h60
  text "PTH" at 6389.72,2553.87 h60
  text "Round" at 6648.86,2553.87 h60
  text "Top Layer - Bottom Layer" at 7024.02,2553.87 h60
  text "191 Total" at 5421.16,2429.55 h60
  text ".Layer_Name" at 577,-858.49 h60
M17 Embedded Cavity:
  text ".Layer_Name" at 577,-858.49 h60
M18 Embedded Assembly:
  text ".Layer_Name" at 577,-858.49 h60
M19 Embedded Keepout:
  text ".Layer_Name" at 577,-858.49 h60

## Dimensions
0,-400 to 1000,-400 on M2 Board Dimensions
0,0 to 0,3450 on M2 Board Dimensions
0,0 to 4950,0 on M2 Board Dimensions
